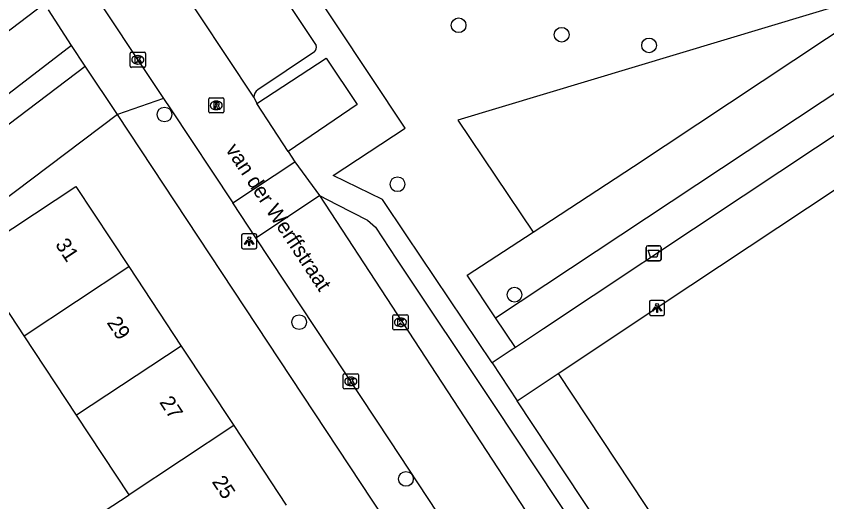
# Model space of a CAD drawing. Extents: x 160037 to 160839, y 385326 to 386441.
# Drawn here: x 160406 to 160459.7, y 385928.2 to 385960.4 of the extents above; entities that cross this region are included whole.
import ezdxf

# ---------------------------------------------------------------- set-up
doc = ezdxf.new("R2010")
doc.units = 0
for name, color, linetype in [('IMGEO_Afvalbak', 7, 'Continuous'), ('IMGEO_Boom', 7, 'Continuous'), ('IMGEO_Groenvoorziening', 7, 'Continuous'), ('IMGEO_Kolk', 7, 'Continuous'), ('IMGEO_Lichtpunt', 7, 'Continuous'), ('IMGEO_Openbare_ruimte_label', 7, 'Continuous'), ('IMGEO_Pand', 7, 'Continuous'), ('IMGEO_Pand_nummerreeks', 7, 'Continuous'), ('IMGEO_Rijbaan_lokaal_open', 7, 'Continuous'), ('IMGEO_Rioolput', 7, 'Continuous'), ('IMGEO_Voetpad_open', 7, 'Continuous')]:
    doc.layers.add(name, color=color, linetype=linetype)

msp = doc.modelspace()

# ---------------------------------------------------------------- linework, layer by layer
at = {"layer": 'IMGEO_Afvalbak'}
for p, q in [((160447.763, 385944.302), (160447.763, 385945.102)), ((160447.763, 385945.102), (160447.763, 385944.302)), ((160447.863, 385945.202), (160448.653, 385945.202)), ((160448.653, 385945.202), (160447.863, 385945.202)), ((160448.753, 385945.102), (160448.753, 385944.302)), ((160448.753, 385944.302), (160448.753, 385945.102)), ((160448.653, 385944.202), (160447.863, 385944.202)), ((160447.863, 385944.202), (160448.653, 385944.202))]:
    msp.add_line(p, q, dxfattribs=at)
msp.add_lwpolyline([(160447.906, 385944.916), (160448.61, 385944.916), (160448.461, 385944.446), (160448.055, 385944.446), (160447.906, 385944.916)], dxfattribs=at)
for centre, start, end in [((160447.863, 385945.102), 90, 180), ((160447.863, 385945.102), 90, 180), ((160448.653, 385945.102), 0, 90), ((160448.653, 385945.102), 360, 90), ((160447.863, 385944.302), 180, 270), ((160447.863, 385944.302), 180, 270), ((160448.653, 385944.302), 270, 0), ((160448.653, 385944.302), 270, 0)]:
    msp.add_arc(centre, 0.1, start, end, dxfattribs=at)
at = {"layer": 'IMGEO_Boom'}
for centre in [(160435.326, 385959.823), (160442.163, 385959.196), (160447.957, 385958.487), (160415.831, 385953.909), (160431.278, 385949.287), (160439.031, 385941.964), (160424.758, 385940.14), (160431.837, 385929.753)]:
    msp.add_circle(centre, 0.489, dxfattribs=at)
at = {"layer": 'IMGEO_Groenvoorziening'}
for points in [[(160461.509, 385961.421), (160435.283, 385953.522), (160440.269, 385946.108)], [(160440.269, 385946.108), (160446.917, 385950.452), (160461.815, 385960.333)], [(160437.782, 385940.438), (160462.758, 385956.981)], [(160437.782, 385940.438), (160435.895, 385943.25), (160440.269, 385946.108)], [(160439.1, 385938.472), (160437.782, 385940.438)], [(160441.922, 385936.735), (160460.168, 385909.183), (160457.496, 385907.331)]]:
    msp.add_lwpolyline(points, dxfattribs=at)
at = {"layer": 'IMGEO_Kolk'}
for p, q in [((160413.561, 385957.109), (160413.561, 385957.961)), ((160413.636, 385958.035), (160414.488, 385958.035)), ((160414.049, 385957.815), (160414.074, 385957.815)), ((160414.562, 385957.961), (160414.562, 385957.109)), ((160414.072, 385957.255), (160414.047, 385957.255)), ((160414.488, 385957.035), (160413.636, 385957.035)), ((160430.973, 385939.709), (160430.973, 385940.561)), ((160431.048, 385940.635), (160431.9, 385940.635)), ((160431.974, 385940.561), (160431.974, 385939.709)), ((160431.461, 385940.415), (160431.486, 385940.415)), ((160431.9, 385939.635), (160431.048, 385939.635)), ((160431.484, 385939.855), (160431.459, 385939.855)), ((160427.757, 385936.717), (160428.609, 385936.717)), ((160427.682, 385935.791), (160427.682, 385936.643)), ((160428.17, 385936.497), (160428.195, 385936.497)), ((160428.683, 385936.643), (160428.683, 385935.791)), ((160428.609, 385935.717), (160427.757, 385935.717)), ((160428.193, 385935.937), (160428.168, 385935.937))]:
    msp.add_line(p, q, dxfattribs=at)
for points in [[(160413.561, 385957.109), (160413.561, 385957.961)], [(160413.636, 385958.035), (160414.488, 385958.035)], [(160413.882, 385957.735), (160414.005, 385957.735), (160414.005, 385957.584), (160414.135, 385957.735), (160414.299, 385957.735), (160414.153, 385957.584), (160414.306, 385957.335), (160414.154, 385957.335), (160414.069, 385957.499), (160414.005, 385957.432), (160414.005, 385957.335), (160413.882, 385957.335), (160413.882, 385957.735)], [(160414.562, 385957.961), (160414.562, 385957.109)], [(160414.488, 385957.035), (160413.636, 385957.035)], [(160430.973, 385939.709), (160430.973, 385940.561)], [(160431.048, 385940.635), (160431.9, 385940.635)], [(160431.974, 385940.561), (160431.974, 385939.709)], [(160431.294, 385940.335), (160431.417, 385940.335), (160431.417, 385940.184), (160431.547, 385940.335), (160431.711, 385940.335), (160431.565, 385940.184), (160431.718, 385939.935), (160431.566, 385939.935), (160431.481, 385940.099), (160431.417, 385940.032), (160431.417, 385939.935), (160431.294, 385939.935), (160431.294, 385940.335)], [(160431.9, 385939.635), (160431.048, 385939.635)], [(160427.757, 385936.717), (160428.609, 385936.717)], [(160427.682, 385935.791), (160427.682, 385936.643)], [(160428.003, 385936.417), (160428.126, 385936.417), (160428.126, 385936.266), (160428.256, 385936.417), (160428.42, 385936.417), (160428.274, 385936.266), (160428.427, 385936.017), (160428.275, 385936.017), (160428.19, 385936.181), (160428.126, 385936.114), (160428.126, 385936.017), (160428.003, 385936.017), (160428.003, 385936.417)], [(160428.683, 385936.643), (160428.683, 385935.791)], [(160428.609, 385935.717), (160427.757, 385935.717)]]:
    msp.add_lwpolyline(points, dxfattribs=at)
for centre, start, end in [((160413.638, 385957.959), 91.552, 178.448), ((160413.638, 385957.959), 91.552, 178.448), ((160414.486, 385957.959), 1.552, 88.448), ((160414.486, 385957.959), 1.552, 88.448), ((160413.638, 385957.111), 181.552, 268.448), ((160413.638, 385957.111), 181.552, 268.448), ((160414.486, 385957.111), 271.552, 358.448), ((160414.486, 385957.111), 271.552, 358.448), ((160431.05, 385940.559), 91.552, 178.448), ((160431.05, 385940.559), 91.552, 178.448), ((160431.898, 385940.559), 1.552, 88.448), ((160431.898, 385940.559), 1.552, 88.448), ((160431.05, 385939.711), 181.552, 268.448), ((160431.05, 385939.711), 181.552, 268.448), ((160431.898, 385939.711), 271.552, 358.448), ((160431.898, 385939.711), 271.552, 358.448), ((160427.759, 385936.641), 91.552, 178.448), ((160427.759, 385936.641), 91.552, 178.448), ((160428.607, 385936.641), 1.552, 88.448), ((160428.607, 385936.641), 1.552, 88.448), ((160427.759, 385935.793), 181.552, 268.448), ((160427.759, 385935.793), 181.552, 268.448), ((160428.607, 385935.793), 271.552, 358.448), ((160428.607, 385935.793), 271.552, 358.448)]:
    msp.add_arc(centre, 0.0765, start, end, dxfattribs=at)
for centre, major_axis, ratio, start_param, end_param in [((160414.048, 385957.535), (-0.387, 0.002), 0.722429, 4.712389, 7.853982), ((160414.073, 385957.535), (-0.39, 0.002), 0.717154, 1.570796, 4.712389), ((160431.46, 385940.135), (-0.387, 0.002), 0.722429, 4.712389, 7.853982), ((160431.485, 385940.135), (-0.39, 0.002), 0.717154, 1.570796, 4.712389), ((160428.169, 385936.217), (-0.387, 0.002), 0.722429, 4.712389, 7.853982), ((160428.194, 385936.217), (-0.39, 0.002), 0.717154, 1.570796, 4.712389)]:
    msp.add_ellipse(centre, major_axis=major_axis, ratio=ratio, start_param=start_param, end_param=end_param, dxfattribs=at)
at = {"layer": 'IMGEO_Lichtpunt'}
for p, q in [((160420.944, 385945.908), (160420.944, 385945.101)), ((160420.944, 385945.908), (160420.944, 385945.101)), ((160421.846, 385946.003), (160421.038, 385946.003)), ((160421.846, 385946.003), (160421.038, 385946.003)), ((160421.94, 385945.101), (160421.94, 385945.908)), ((160421.94, 385945.101), (160421.94, 385945.908)), ((160421.038, 385945.007), (160421.846, 385945.007)), ((160421.038, 385945.007), (160421.846, 385945.007)), ((160448.888, 385941.587), (160448.08, 385941.587)), ((160448.888, 385941.587), (160448.08, 385941.587)), ((160447.986, 385941.492), (160447.986, 385940.685)), ((160447.986, 385941.492), (160447.986, 385940.685)), ((160448.982, 385940.685), (160448.982, 385941.492)), ((160448.982, 385940.685), (160448.982, 385941.492)), ((160448.08, 385940.591), (160448.888, 385940.591)), ((160448.08, 385940.591), (160448.888, 385940.591))]:
    msp.add_line(p, q, dxfattribs=at)
for points in [[(160421.318, 385945.572), (160421.357, 385945.544), (160421.169, 385945.282), (160421.131, 385945.309), (160421.318, 385945.572)], [(160421.42, 385945.524), (160421.467, 385945.524), (160421.467, 385945.202), (160421.42, 385945.202), (160421.42, 385945.524)], [(160421.53, 385945.544), (160421.568, 385945.571), (160421.755, 385945.309), (160421.716, 385945.281), (160421.53, 385945.544)], [(160448.36, 385941.156), (160448.399, 385941.128), (160448.211, 385940.866), (160448.173, 385940.893), (160448.36, 385941.156)], [(160448.462, 385941.108), (160448.509, 385941.108), (160448.509, 385940.786), (160448.462, 385940.786), (160448.462, 385941.108)], [(160448.572, 385941.128), (160448.61, 385941.155), (160448.797, 385940.893), (160448.758, 385940.865), (160448.572, 385941.128)]]:
    msp.add_lwpolyline(points, dxfattribs=at)
for centre in [(160421.443, 385945.706), (160448.485, 385941.29)]:
    msp.add_circle(centre, 0.0994, dxfattribs=at)
for centre, start, end in [((160421.038, 385945.908), 90, 180), ((160421.038, 385945.908), 90, 180), ((160421.846, 385945.908), 0, 90), ((160421.846, 385945.908), 0, 90), ((160421.038, 385945.101), 180, 270), ((160421.038, 385945.101), 180, 270), ((160421.846, 385945.101), 270, 0), ((160421.846, 385945.101), 270, 360), ((160448.08, 385941.492), 90, 180), ((160448.08, 385941.492), 90, 180), ((160448.888, 385941.492), 0, 90), ((160448.888, 385941.492), 0, 90), ((160448.08, 385940.685), 180, 270), ((160448.08, 385940.685), 180, 270), ((160448.888, 385940.685), 270, 0), ((160448.888, 385940.685), 270, 360)]:
    msp.add_arc(centre, 0.0946, start, end, dxfattribs=at)
at = {"layer": 'IMGEO_Pand'}
for points in [[(160401.214, 385951.993), (160399.179, 385954.642), (160403.975, 385958.329), (160407.871, 385961.257)], [(160409.657, 385958.483), (160408.137, 385960.844)], [(160409.657, 385958.483), (160406.01, 385955.68), (160401.214, 385951.993)], [(160406.521, 385939.244), (160403.008, 385944.565), (160409.941, 385949.143), (160413.454, 385943.822)], [(160406.521, 385939.244), (160413.454, 385943.822)], [(160413.454, 385943.822), (160416.934, 385938.552)], [(160410.001, 385933.975), (160406.521, 385939.244)], [(160416.934, 385938.552), (160410.001, 385933.975)], [(160416.934, 385938.552), (160420.415, 385933.281)], [(160413.482, 385928.703), (160410.001, 385933.975)], [(160420.415, 385933.281), (160413.482, 385928.703)], [(160420.415, 385933.281), (160423.895, 385928.01)], [(160415.024, 385922.152), (160413.153, 385920.917), (160409.673, 385926.188), (160413.482, 385928.703)]]:
    msp.add_lwpolyline(points, dxfattribs=at)
at = {"layer": 'IMGEO_Rijbaan_lokaal_open'}
for points in [[(160421.745, 385955.056), (160412.791, 385968.568)], [(160410.294, 385963.178), (160415.771, 385954.973)], [(160395.589, 385945.741), (160399.737, 385948.905), (160410.573, 385957.101)], [(160412.72, 385953.919), (160410.573, 385957.101)], [(160415.771, 385954.973), (160416.233, 385954.281), (160420.355, 385948.051)], [(160421.745, 385955.056), (160421.957, 385954.628)], [(160424.019, 385951.445), (160421.957, 385954.628)], [(160412.72, 385953.919), (160403.58, 385947.044), (160403.693, 385946.835), (160390.343, 385936.662)], [(160424.019, 385951.445), (160424.467, 385950.771)], [(160420.355, 385948.051), (160424.467, 385950.771)], [(160424.467, 385950.771), (160426.116, 385948.529)], [(160421.889, 385945.733), (160426.116, 385948.529)], [(160426.116, 385948.529), (160440.493, 385926.528), (160454.847, 385904.844), (160457.938, 385900.153)], [(160421.889, 385945.733), (160420.355, 385948.051)], [(160455.401, 385894.928), (160445.725, 385909.593), (160430.791, 385932.279), (160421.889, 385945.733)]]:
    msp.add_lwpolyline(points, dxfattribs=at)
at = {"layer": 'IMGEO_Rioolput'}
for p, q in [((160418.835, 385955.013), (160419.687, 385955.013)), ((160418.76, 385954.087), (160418.76, 385954.939)), ((160419.248, 385954.793), (160419.273, 385954.793)), ((160419.761, 385954.939), (160419.761, 385954.087)), ((160419.687, 385954.013), (160418.835, 385954.013)), ((160419.271, 385954.233), (160419.246, 385954.233))]:
    msp.add_line(p, q, dxfattribs=at)
for points in [[(160418.835, 385955.013), (160419.687, 385955.013)], [(160418.76, 385954.087), (160418.76, 385954.939)], [(160419.349, 385954.711), (160419.097, 385954.713), (160419.097, 385954.313)], [(160419.097, 385954.313), (160419.221, 385954.313), (160419.221, 385954.475), (160419.232, 385954.475)], [(160419.275, 385954.632), (160419.221, 385954.632), (160419.221, 385954.551)], [(160419.221, 385954.551), (160419.273, 385954.551)], [(160419.279, 385954.446), (160419.35, 385954.313), (160419.49, 385954.313), (160419.425, 385954.439)], [(160419.761, 385954.939), (160419.761, 385954.087)], [(160419.687, 385954.013), (160418.835, 385954.013)]]:
    msp.add_lwpolyline(points, dxfattribs=at)
for centre, radius, start, end in [((160418.837, 385954.937), 0.0765, 91.552, 178.448), ((160418.837, 385954.937), 0.0765, 91.552, 178.448), ((160419.685, 385954.937), 0.0765, 1.552, 88.448), ((160419.685, 385954.937), 0.0765, 1.552, 88.448), ((160419.231, 385954.422), 0.0533, 26.0293, 88.6989), ((160419.257, 385954.74), 0.19, 274.7715, 282.9687), ((160419.281, 385954.536), 0.0964, 77.0061, 93.1865), ((160419.295, 385954.593), 0.0378, 276.6634, 79.6772), ((160419.348, 385954.601), 0.109, 350.3612, 89.416), ((160419.346, 385954.601), 0.112, 277.5842, 350.9817), ((160419.33, 385954.386), 0.108, 29.5134, 73.7905), ((160418.837, 385954.089), 0.0765, 181.552, 268.448), ((160418.837, 385954.089), 0.0765, 181.552, 268.448), ((160419.685, 385954.089), 0.0765, 271.552, 358.448), ((160419.685, 385954.089), 0.0765, 271.552, 358.448)]:
    msp.add_arc(centre, radius, start, end, dxfattribs=at)
for centre, major_axis, ratio, start_param, end_param in [((160419.247, 385954.513), (-0.387, 0.002), 0.722429, 4.712389, 7.853982), ((160419.272, 385954.513), (-0.39, 0.002), 0.717154, 1.570796, 4.712389)]:
    msp.add_ellipse(centre, major_axis=major_axis, ratio=ratio, start_param=start_param, end_param=end_param, dxfattribs=at)
at = {"layer": 'IMGEO_Voetpad_open'}
for points in [[(160417.624, 385970.926), (160425.879, 385958.487)], [(160437.557, 385937.447), (160431.847, 385945.931), (160430.276, 385948.273), (160427.012, 385949.858), (160431.791, 385953.009), (160424.868, 385963.428)], [(160441.922, 385936.735), (160442.693, 385937.248), (160448.756, 385941.281), (160462.321, 385950.277), (160475.564, 385959.077), (160478.178, 385955.304)], [(160410.573, 385957.101), (160409.657, 385958.483)], [(160421.957, 385954.628), (160426.554, 385957.65), (160428.613, 385954.572), (160424.019, 385951.445)], [(160425.766, 385958.058), (160422.017, 385955.547)], [(160462.758, 385956.981), (160463.431, 385954.588), (160461.423, 385953.3), (160454.194, 385948.496), (160440.964, 385939.71), (160439.1, 385938.472)], [(160415.771, 385954.973), (160412.72, 385953.919)], [(160451.889, 385894.583), (160412.72, 385953.919)], [(160426.116, 385948.529), (160427.26, 385947.948), (160429.291, 385946.9), (160429.816, 385946.429), (160431.209, 385944.322), (160437.68, 385934.623), (160450.262, 385915.651), (160457.246, 385905.168)], [(160439.1, 385938.472), (160438.807, 385938.277), (160437.557, 385937.447)], [(160437.557, 385937.447), (160439.216, 385934.935)], [(160439.216, 385934.935), (160441.922, 385936.735)], [(160457.496, 385907.331), (160439.216, 385934.935)]]:
    msp.add_lwpolyline(points, dxfattribs=at)
for centre, radius, start, end in [((160425.526, 385958.35), 0.378, 309.3146, 21.172), ((160422.436, 385954.994), 0.694, 127.1544, 174.8752)]:
    msp.add_arc(centre, radius, start, end, dxfattribs=at)

# ---------------------------------------------------------------- texts
at = {"layer": 'IMGEO_Openbare_ruimte_label'}
msp.add_text('van der Werffstraat', height=1, rotation=303.4994, dxfattribs=at).set_placement((160419.844, 385951.582))
at = {"layer": 'IMGEO_Pand_nummerreeks'}
for s, rotation, p in [('31', 303.4362, (160408.553, 385945.292)), ('29', 303.4362, (160411.974, 385940.112)), ('27', 303.4362, (160415.458, 385934.836)), ('25', 303.4376, (160418.941, 385929.561))]:
    msp.add_text(s, height=1, rotation=rotation, dxfattribs=at).set_placement(p)

doc.saveas('drawing.dxf')
